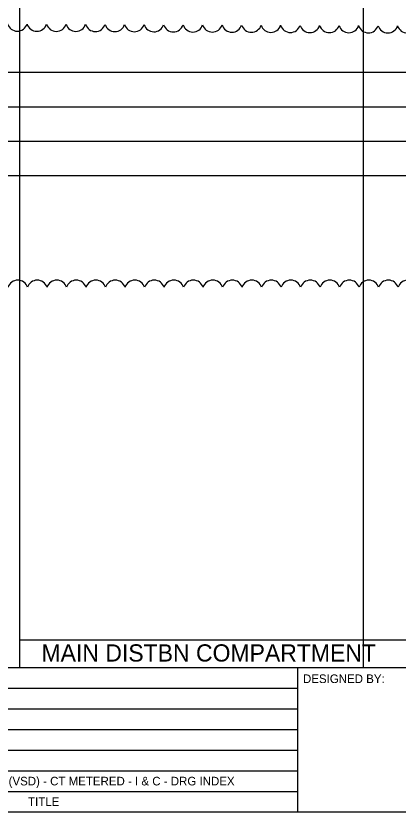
# Model space of a CAD drawing. Extents: x 0 to 841, y 0 to 594.
# Drawn here: x 299 to 410.2, y 15 to 246.4 of the extents above; entities that cross this region are included whole.
import ezdxf

# ---------------------------------------------------------------- set-up
doc = ezdxf.new("R2010")
doc.units = 0
doc.layers.add('A1BORDER', color=7, linetype='Continuous')
doc.layers.add('Level 1', color=7, linetype='Continuous')

msp = doc.modelspace()

# ---------------------------------------------------------------- linework, layer by layer
at = {"layer": 'A1BORDER'}
for p, q in [((28, 57), (829, 57)), ((381, 15), (381, 57)), ((213, 51), (381, 51)), ((213, 45), (381, 45)), ((213, 39), (381, 39)), ((213, 33), (381, 33)), ((213, 27), (381, 27)), ((213, 21), (381, 21)), ((829, 15), (28, 15))]:
    msp.add_line(p, q, dxfattribs=at)
at = {"layer": 'Level 1'}
for p, q in [((300, 572.5), (300, 57)), ((400, 572.5), (400, 57)), ((280, 230), (628.75, 230)), ((280, 220), (685, 220)), ((280, 210), (628.75, 210)), ((280, 200), (685, 200)), ((400, 65), (300, 65)), ((560, 65), (400, 65))]:
    msp.add_line(p, q, dxfattribs=at)
for centre, start, end in [((299.39, 244.94), 197.2245, 342.2245), ((305.06, 244.91), 197.2245, 342.2245), ((310.74, 244.88), 197.2245, 342.2245), ((316.41, 244.85), 197.2245, 342.2245), ((322.09, 244.83), 197.2245, 342.2245), ((327.76, 244.8), 197.2245, 342.2245), ((333.44, 244.77), 197.2245, 342.2245), ((339.11, 244.75), 197.2245, 342.2245), ((344.79, 244.72), 197.2245, 342.2245), ((350.46, 244.69), 197.2245, 342.2245), ((356.14, 244.66), 197.2245, 342.2245), ((361.81, 244.64), 197.2245, 342.2245), ((367.49, 244.61), 197.2245, 342.2245), ((373.16, 244.58), 197.2245, 342.2245), ((378.83, 244.55), 197.2245, 342.2245), ((384.51, 244.53), 197.2245, 342.2245), ((390.18, 244.5), 197.2245, 342.2245), ((395.86, 244.47), 197.2245, 342.2245), ((401.53, 244.44), 197.2245, 342.2245), ((407.21, 244.42), 197.2245, 342.2245), ((412.88, 244.39), 197.2245, 342.2245), ((299.52, 166.61), 17.5, 162.5), ((305.19, 166.61), 17.5, 162.5), ((310.87, 166.61), 17.5, 162.5), ((316.54, 166.61), 17.5, 162.5), ((322.22, 166.61), 17.5, 162.5), ((327.89, 166.61), 17.5, 162.5), ((333.56, 166.61), 17.5, 162.5), ((339.24, 166.61), 17.5, 162.5), ((344.91, 166.61), 17.5, 162.5), ((350.59, 166.61), 17.5, 162.5), ((356.26, 166.61), 17.5, 162.5), ((361.94, 166.61), 17.5, 162.5), ((367.61, 166.61), 17.5, 162.5), ((373.29, 166.61), 17.5, 162.5), ((378.96, 166.61), 17.5, 162.5), ((384.64, 166.61), 17.5, 162.5), ((390.31, 166.61), 17.5, 162.5), ((395.99, 166.61), 17.5, 162.5), ((401.66, 166.61), 17.5, 162.5), ((407.34, 166.61), 17.5, 162.5), ((413.01, 166.61), 17.5, 162.5)]:
    msp.add_arc(centre, 2.98, start, end, dxfattribs=at)

# ---------------------------------------------------------------- texts
at = {"layer": 'A1BORDER'}
for s, p in [('DESIGNED BY:', (382.5, 52.5)), ('TITLE', (302.5, 16.81))]:
    msp.add_text(s, height=2.5, dxfattribs=at).set_placement(p)
at = {"layer": 'Level 1'}
for s, height, p in [('MAIN DISTBN COMPARTMENT', 5, (306.42, 58.75)), ('STD SPS - PUMP STN 30kW TO 160kW (VSD) - CT METERED - I & C - DRG INDEX', 2.5, (235, 22.75))]:
    msp.add_text(s, height=height, dxfattribs=at).set_placement(p)

doc.saveas('drawing.dxf')
